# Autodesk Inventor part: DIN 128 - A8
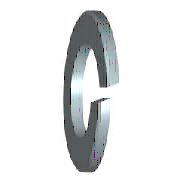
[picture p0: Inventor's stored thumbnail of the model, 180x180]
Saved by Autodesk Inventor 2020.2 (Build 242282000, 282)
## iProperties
Manager: www.cadconsulting.pl
Company: Fabian Stasiak CAD Consulting
IsCustomPart: 0
Created: 2010-02
Part Number: DIN 128 - A8
Material: Stal, miękka
Description: Podkładka sprężysta
Document SubType Name: Modeling
Standard: DIN 128
Designer: F.Stasiak
Standard Revision: 1994
Standards Organization: DIN
Language: pl-PL
Size Designation: A8
Categories: <MemberInstance><Categories><Category DisplayName="Mocowania" InternalName="e4da775c-781d-43d5-af7c-5136215cf5a6" Mnemonic="FSTN"><Category DisplayName="Podkład
Density: 1 g/cm^3
Appearance: Metal-Stal
Author: F.Stasiak
Subject: Zbiór ćwiczeń. Autodesk Inventor 2020. Kurs podstawowy
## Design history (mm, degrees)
sketch "Sketch1"
  geometry: C1 r 7.4 at (0, 0); C2 r 4.25 at (0, 0); 1 further point
  constraints: 2 centre point, 2 coincident
  dimensions: "d0" = 8.5 diameter of C2 (= SD1); "d1" = 14.8 diameter of C1 (= SD2)
extrude "Body" new body sketch "Sketch1" distance "d2" = 1.6 (= SD); taper "d3" = 0 deg
fillet "Fillet" dims "d13" = 0.5 (= R)
sketch "Sketch2"
  geometry: L1 (0, -4.25)-(0, 4.25) reference; L2 (1.6, 7.4)-(1.6, -7.4) reference; L3 (-1.2, 0)-(7.2, 0) reference; L4 (0, -0.32)-(1.6, 0.604); L5 (0, 0.32)-(1.6, 1.244)
  constraints: 4 end point, 4 point on line, 1 parallel
  dimensions: "d4" = 0.32 distance from line of L3 L4.start (= 0.2 x SD); "d5" = 0.32 distance from line of L3 L5.start (= 0.2 x SD); "d6" = 60 deg angle of L2 L4 (= FAWI)
extrude "Cut" cut sketch "Sketch2" stored distance "d7" = 1.6 (= SD); taper "d8" = 0 deg
workaxis "Work Axis1"
workplane "Work Plane1"
body "Solid1"
other parameters: "SD1" = 8.5 [user parameter; used in 1 equation term], "SD2" = 14.8 [user parameter; used in 1 equation term], "SD" = 1.6 [user parameter; used in 4 equation terms], "FAWI" = 60 deg [user parameter; used in 1 equation term], "d9" = 0, "d10" = 0, "d11" = 0, "d12" = 0, "R" = 0.5 [user parameter; used in 1 equation term], "NND" = 8 [user parameter]
